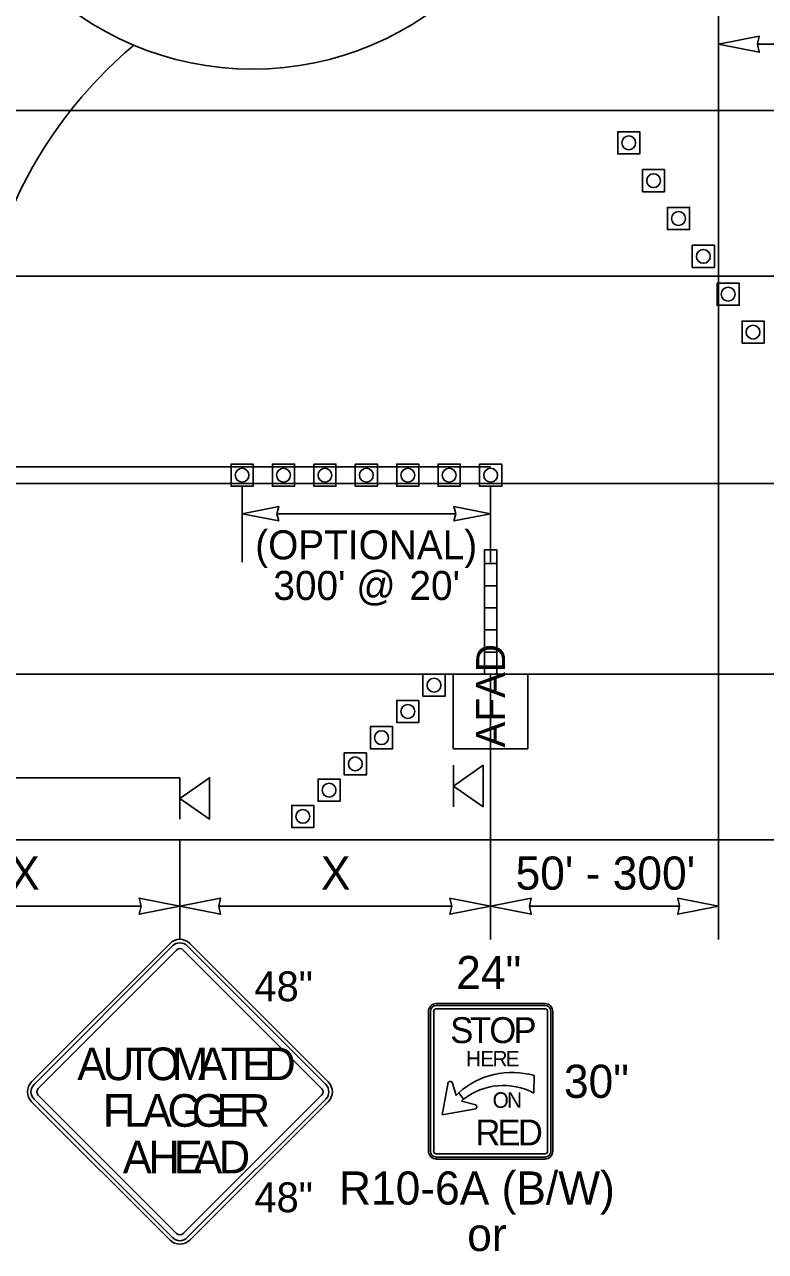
# Model space of a CAD drawing. Extents: x 99999.1 to 100095.7, y 99995 to 100010.7.
# Drawn here: x 100003.152 to 100004.94, y 100004.739 to 100007.7 of the extents above; entities that cross this region are included whole.
import ezdxf

# ---------------------------------------------------------------- set-up
doc = ezdxf.new("R2010")
doc.units = 0
for name, color, linetype in [('RD_ED_ShoulderPavedEdge', 7, 'Continuous'), ('RD_MK_LineDblYellowCenter', 7, 'Continuous'), ('RD_MK_LineEdgeWhite', 7, 'Continuous'), ('RD_MK_LineNoPass', 7, 'Continuous'), ('RD_MK_LineSkipCenter', 7, 'Continuous'), ('TR_SN_ConstructionSigns', 7, 'Continuous'), ('TR_WZ_AFAD', 7, 'Continuous'), ('TR_WZ_PortableSignMountBlk-Org', 7, 'Continuous'), ('TR_WZ_PortableSignMountBlk-Wht', 7, 'Continuous'), ('TR_WZ_TrafficCone', 7, 'Continuous'), ('TR_WZ_WorkZoneDetails', 7, 'Continuous'), ('TR_WZ_WorkZoneTextCurrent', 7, 'Continuous')]:
    doc.layers.add(name, color=color, linetype=linetype)

msp = doc.modelspace()

# ---------------------------------------------------------------- linework, layer by layer
at = {"layer": 'RD_ED_ShoulderPavedEdge'}
for p, q in [((100000.1076, 100007.4923), (100015.6424, 100007.4923)), ((100000.1076, 100005.7323), (100015.6424, 100005.7323))]:
    msp.add_line(p, q, dxfattribs=at)
at = {"layer": 'RD_MK_LineDblYellowCenter'}
for p, q in [((100000.1282, 100006.6323), (100003.4767, 100006.6323)), ((100000.0869, 100006.5923), (100003.4767, 100006.5923))]:
    msp.add_line(p, q, dxfattribs=at)
at = {"layer": 'RD_MK_LineEdgeWhite'}
for p, q in [((100000.1076, 100007.0923), (100015.6424, 100007.0923)), ((100000.1076, 100006.1323), (100015.6424, 100006.1323))]:
    msp.add_line(p, q, dxfattribs=at)
at = {"layer": 'RD_MK_LineNoPass'}
msp.add_line((100003.4767, 100006.6323), (100004.2767, 100006.6323), dxfattribs=at)
at = {"layer": 'RD_MK_LineSkipCenter'}
msp.add_lwpolyline([(100011.15, 100006.5923), (100003.4767, 100006.5923)], dxfattribs=at)
at = {"layer": 'TR_SN_ConstructionSigns'}
for p, q in [((100003.5028, 100005.4824), (100003.1687, 100005.1483)), ((100003.5088, 100005.4765), (100003.1746, 100005.1424)), ((100003.1846, 100005.1324), (100003.5187, 100005.4665)), ((100003.5346, 100005.4665), (100003.8687, 100005.1324)), ((100003.8787, 100005.1424), (100003.5445, 100005.4765)), ((100003.8846, 100005.1483), (100003.5505, 100005.4824)), ((100004.4079, 100005.3373), (100004.1454, 100005.3373)), ((100004.1454, 100005.3373), (100004.4079, 100005.3373)), ((100004.4079, 100005.3373), (100004.1454, 100005.3373)), ((100004.1454, 100005.3373), (100004.4079, 100005.3373)), ((100004.1267, 100005.3186), (100004.1267, 100004.9811)), ((100004.1267, 100004.9811), (100004.1267, 100005.3186)), ((100004.1267, 100005.3186), (100004.1267, 100004.9811)), ((100004.1267, 100004.9811), (100004.1267, 100005.3186)), ((100004.1313, 100005.3186), (100004.1313, 100004.9811)), ((100004.1392, 100004.9811), (100004.1392, 100005.3186)), ((100004.4079, 100005.3326), (100004.1454, 100005.3326)), ((100004.1454, 100005.3248), (100004.4079, 100005.3248)), ((100004.4142, 100005.3186), (100004.4142, 100004.9811)), ((100004.422, 100004.9811), (100004.422, 100005.3186)), ((100004.4267, 100004.9811), (100004.4267, 100005.3186)), ((100004.4267, 100005.3186), (100004.4267, 100004.9811)), ((100004.4267, 100004.9811), (100004.4267, 100005.3186)), ((100004.4267, 100005.3186), (100004.4267, 100004.9811)), ((100004.3816, 100005.1635), (100004.3813, 100005.1216)), ((100004.3813, 100005.1216), (100004.3816, 100005.1635)), ((100004.1595, 100005.0686), (100004.1731, 100005.143)), ((100004.1839, 100005.1479), (100004.1933, 100005.1154)), ((100003.1687, 100005.1006), (100003.5028, 100004.7665)), ((100003.1746, 100005.1066), (100003.5088, 100004.7725)), ((100003.5187, 100004.7824), (100003.1846, 100005.1165)), ((100003.8687, 100005.1165), (100003.5346, 100004.7824)), ((100003.5445, 100004.7725), (100003.8787, 100005.1066)), ((100003.5505, 100004.7665), (100003.8846, 100005.1006)), ((100004.1933, 100005.1154), (100004.1996, 100005.1218)), ((100004.1996, 100005.1218), (100004.2113, 100005.1069)), ((100004.1996, 100005.1218), (100004.2113, 100005.1069)), ((100004.2113, 100005.1069), (100004.2066, 100005.1021)), ((100004.2066, 100005.1021), (100004.2408, 100005.0929)), ((100004.2406, 100005.0837), (100004.1595, 100005.0686)), ((100004.4079, 100004.9748), (100004.1454, 100004.9748)), ((100004.1454, 100004.967), (100004.4079, 100004.967)), ((100004.1454, 100004.9623), (100004.4079, 100004.9623)), ((100004.4079, 100004.9623), (100004.1454, 100004.9623)), ((100004.1454, 100004.9623), (100004.4079, 100004.9623)), ((100004.4079, 100004.9623), (100004.1454, 100004.9623))]:
    msp.add_line(p, q, dxfattribs=at)
for centre, radius, start, end in [((100003.5267, 100005.4586), 0.0338, 45, 135), ((100003.5267, 100005.4586), 0.0253, 45, 135), ((100003.5267, 100005.4586), 0.0113, 45, 135), ((100004.1454, 100005.3186), 0.0187, 90, 180), ((100004.1454, 100005.3186), 0.0187, 90, 180), ((100004.1454, 100005.3186), 0.0187, 90, 180), ((100004.1454, 100005.3186), 0.0187, 90, 180), ((100004.4079, 100005.3186), 0.0187, 0, 90), ((100004.4079, 100005.3186), 0.0187, 0, 90), ((100004.4079, 100005.3186), 0.0187, 0, 90), ((100004.4079, 100005.3186), 0.0187, 0, 90), ((100004.1454, 100005.3186), 0.0141, 90, 180), ((100004.1454, 100005.3186), 0.00625, 90, 180), ((100004.4079, 100005.3186), 0.0141, 0, 90), ((100004.4079, 100005.3186), 0.00625, 0, 90), ((100004.3279, 100004.9804), 0.1909, 73.6434, 132.2131), ((100004.3279, 100004.9804), 0.1909, 73.6434, 132.2131), ((100003.1925, 100005.1245), 0.0338, 135, 225), ((100003.1925, 100005.1245), 0.0253, 135, 225), ((100003.1925, 100005.1245), 0.0113, 135, 225), ((100003.8608, 100005.1245), 0.0113, 315, 45), ((100003.8608, 100005.1245), 0.0253, 315, 45), ((100003.8608, 100005.1245), 0.0338, 315, 45), ((100004.3078, 100004.981), 0.1586, 62.4149, 127.4769), ((100004.3078, 100004.981), 0.1586, 62.4149, 127.4769), ((100004.1454, 100004.9811), 0.0187, 180, 270), ((100004.1454, 100004.9811), 0.0187, 180, 270), ((100004.1454, 100004.9811), 0.0187, 180, 270), ((100004.1454, 100004.9811), 0.0187, 180, 270), ((100004.1454, 100004.9811), 0.0141, 180, 270), ((100004.1454, 100004.9811), 0.00625, 180, 270), ((100004.4079, 100004.9811), 0.0187, 270, 0), ((100004.4079, 100004.9811), 0.0187, 270, 0), ((100004.4079, 100004.9811), 0.0187, 270, 0), ((100004.4079, 100004.9811), 0.0141, 270, 0), ((100004.4079, 100004.9811), 0.00625, 270, 0), ((100004.4079, 100004.9811), 0.0187, 270, 0), ((100003.5267, 100004.7904), 0.0253, 225, 315), ((100003.5267, 100004.7904), 0.0113, 225, 315), ((100003.5267, 100004.7904), 0.0338, 225, 315)]:
    msp.add_arc(centre, radius, start, end, dxfattribs=at)
for centre, major_axis, ratio, start_param, end_param in [((100004.1795, 100005.1431), (-0.00647, -0.00009), 0.989437, 3.962549, 6.283185), ((100004.2384, 100005.0883), (-0.0046, 0.00239), 0.999053, 2.490568, 4.712389)]:
    msp.add_ellipse(centre, major_axis=major_axis, ratio=ratio, start_param=start_param, end_param=end_param, dxfattribs=at)
at = {"layer": 'TR_WZ_AFAD'}
for p, q in [((100004.2916, 100006.399), (100004.2916, 100006.4323)), ((100004.2616, 100006.399), (100004.2616, 100006.3457)), ((100004.2616, 100006.399), (100004.2766, 100006.399)), ((100004.2766, 100006.399), (100004.2916, 100006.399)), ((100004.2916, 100006.3457), (100004.2916, 100006.399)), ((100004.2616, 100006.3457), (100004.2616, 100006.2923)), ((100004.2766, 100006.3457), (100004.2616, 100006.3457)), ((100004.2916, 100006.3457), (100004.2766, 100006.3457)), ((100004.2916, 100006.2923), (100004.2916, 100006.3457)), ((100004.2616, 100006.2923), (100004.2616, 100006.239)), ((100004.2616, 100006.2923), (100004.2766, 100006.2923)), ((100004.2766, 100006.2923), (100004.2916, 100006.2923)), ((100004.2916, 100006.239), (100004.2916, 100006.2923)), ((100004.2766, 100006.239), (100004.2616, 100006.239)), ((100004.2616, 100006.239), (100004.2616, 100006.1857)), ((100004.2916, 100006.239), (100004.2766, 100006.239)), ((100004.2916, 100006.1857), (100004.2916, 100006.239)), ((100004.2616, 100006.1857), (100004.2616, 100006.1323)), ((100004.1866, 100005.9523), (100004.1866, 100006.1323)), ((100004.1866, 100006.1323), (100004.3666, 100006.1323)), ((100004.27, 100006.1323), (100004.1866, 100006.1323)), ((100004.1866, 100006.1323), (100004.1866, 100005.9523)), ((100004.2616, 100006.1323), (100004.27, 100006.1323)), ((100004.27, 100006.1323), (100004.2766, 100006.1323)), ((100004.3666, 100006.1323), (100004.3666, 100005.9523)), ((100004.3666, 100005.9523), (100004.3666, 100006.1323)), ((100004.3666, 100005.9523), (100004.1866, 100005.9523)), ((100004.1866, 100005.9523), (100004.3666, 100005.9523))]:
    msp.add_line(p, q, dxfattribs=at)
for points in [[(100004.2916, 100006.4323), (100004.2616, 100006.4323), (100004.2616, 100006.399)], [(100004.2916, 100006.1323), (100004.2916, 100006.4323), (100004.2616, 100006.4323), (100004.2616, 100006.1323)], [(100004.2916, 100006.399), (100004.2766, 100006.399), (100004.2616, 100006.399)], [(100004.2616, 100006.3457), (100004.2766, 100006.3457), (100004.2916, 100006.3457)], [(100004.2916, 100006.2923), (100004.2766, 100006.2923), (100004.2616, 100006.2923)], [(100004.2616, 100006.239), (100004.2766, 100006.239), (100004.2916, 100006.239)], [(100004.2916, 100006.1857), (100004.2766, 100006.1857), (100004.2616, 100006.1857)], [(100004.2616, 100006.1857), (100004.2766, 100006.1857), (100004.2916, 100006.1857)], [(100004.2766, 100006.1323), (100004.2833, 100006.1323), (100004.2916, 100006.1323), (100004.2916, 100006.1857)], [(100004.3666, 100006.1323), (100004.2833, 100006.1323), (100004.27, 100006.1323)]]:
    msp.add_lwpolyline(points, dxfattribs=at)
at = {"layer": 'TR_WZ_PortableSignMountBlk-Org'}
msp.add_line((100003.5267, 100005.7824), (100003.5267, 100005.8824), dxfattribs=at)
msp.add_lwpolyline([(100003.5267, 100005.8323), (100003.5985, 100005.8824), (100003.5985, 100005.7824)], close=True, dxfattribs=at)
at = {"layer": 'TR_WZ_PortableSignMountBlk-Wht'}
msp.add_line((100004.1867, 100005.8123), (100004.1867, 100005.9123), dxfattribs=at)
msp.add_lwpolyline([(100004.1867, 100005.8622), (100004.2585, 100005.9123), (100004.2585, 100005.8123)], close=True, dxfattribs=at)
at = {"layer": 'TR_WZ_TrafficCone'}
for points in [[(100004.6367, 100007.4411), (100004.5834, 100007.4411), (100004.5834, 100007.3877), (100004.6367, 100007.3877), (100004.6367, 100007.4411)], [(100004.6367, 100007.3877), (100004.5834, 100007.3877), (100004.5834, 100007.4411), (100004.6367, 100007.4411), (100004.6367, 100007.3877)], [(100004.6367, 100007.4411), (100004.5834, 100007.4411), (100004.5834, 100007.3877), (100004.6367, 100007.3877), (100004.6367, 100007.4411)], [(100004.6367, 100007.3877), (100004.5834, 100007.3877), (100004.5834, 100007.4411), (100004.6367, 100007.4411), (100004.6367, 100007.3877)], [(100004.6967, 100007.3497), (100004.6434, 100007.3497), (100004.6434, 100007.2964), (100004.6967, 100007.2964), (100004.6967, 100007.3497)], [(100004.6967, 100007.2964), (100004.6434, 100007.2964), (100004.6434, 100007.3497), (100004.6967, 100007.3497), (100004.6967, 100007.2964)], [(100004.6967, 100007.3497), (100004.6434, 100007.3497), (100004.6434, 100007.2964), (100004.6967, 100007.2964), (100004.6967, 100007.3497)], [(100004.6967, 100007.2964), (100004.6434, 100007.2964), (100004.6434, 100007.3497), (100004.6967, 100007.3497), (100004.6967, 100007.2964)], [(100004.7567, 100007.2584), (100004.7034, 100007.2584), (100004.7034, 100007.2051), (100004.7567, 100007.2051), (100004.7567, 100007.2584)], [(100004.7567, 100007.2051), (100004.7034, 100007.2051), (100004.7034, 100007.2584), (100004.7567, 100007.2584), (100004.7567, 100007.2051)], [(100004.7567, 100007.2584), (100004.7034, 100007.2584), (100004.7034, 100007.2051), (100004.7567, 100007.2051), (100004.7567, 100007.2584)], [(100004.7567, 100007.2051), (100004.7034, 100007.2051), (100004.7034, 100007.2584), (100004.7567, 100007.2584), (100004.7567, 100007.2051)], [(100004.8167, 100007.1671), (100004.7634, 100007.1671), (100004.7634, 100007.1137), (100004.8167, 100007.1137), (100004.8167, 100007.1671)], [(100004.8167, 100007.1137), (100004.7634, 100007.1137), (100004.7634, 100007.1671), (100004.8167, 100007.1671), (100004.8167, 100007.1137)], [(100004.8234, 100007.0757), (100004.8767, 100007.0757), (100004.8767, 100007.0224), (100004.8234, 100007.0224), (100004.8234, 100007.0757)], [(100004.8234, 100007.0224), (100004.8767, 100007.0224), (100004.8767, 100007.0757), (100004.8234, 100007.0757), (100004.8234, 100007.0224)], [(100004.8834, 100006.9844), (100004.9367, 100006.9844), (100004.9367, 100006.9311), (100004.8834, 100006.9311), (100004.8834, 100006.9844)], [(100004.8834, 100006.9311), (100004.9367, 100006.9311), (100004.9367, 100006.9844), (100004.8834, 100006.9844), (100004.8834, 100006.9311)], [(100003.7033, 100006.639), (100003.65, 100006.639), (100003.65, 100006.5857), (100003.7033, 100006.5857), (100003.7033, 100006.639)], [(100003.7033, 100006.5857), (100003.65, 100006.5857), (100003.65, 100006.639), (100003.7033, 100006.639), (100003.7033, 100006.5857)], [(100003.8033, 100006.639), (100003.75, 100006.639), (100003.75, 100006.5857), (100003.8033, 100006.5857), (100003.8033, 100006.639)], [(100003.8033, 100006.5857), (100003.75, 100006.5857), (100003.75, 100006.639), (100003.8033, 100006.639), (100003.8033, 100006.5857)], [(100003.9033, 100006.639), (100003.85, 100006.639), (100003.85, 100006.5857), (100003.9033, 100006.5857), (100003.9033, 100006.639)], [(100003.9033, 100006.5857), (100003.85, 100006.5857), (100003.85, 100006.639), (100003.9033, 100006.639), (100003.9033, 100006.5857)], [(100004.0033, 100006.639), (100003.95, 100006.639), (100003.95, 100006.5857), (100004.0033, 100006.5857), (100004.0033, 100006.639)], [(100004.0033, 100006.5857), (100003.95, 100006.5857), (100003.95, 100006.639), (100004.0033, 100006.639), (100004.0033, 100006.5857)], [(100004.1033, 100006.639), (100004.05, 100006.639), (100004.05, 100006.5857), (100004.1033, 100006.5857), (100004.1033, 100006.639)], [(100004.1033, 100006.5857), (100004.05, 100006.5857), (100004.05, 100006.639), (100004.1033, 100006.639), (100004.1033, 100006.5857)], [(100004.2033, 100006.639), (100004.15, 100006.639), (100004.15, 100006.5857), (100004.2033, 100006.5857), (100004.2033, 100006.639)], [(100004.2033, 100006.5857), (100004.15, 100006.5857), (100004.15, 100006.639), (100004.2033, 100006.639), (100004.2033, 100006.5857)], [(100004.3033, 100006.639), (100004.25, 100006.639), (100004.25, 100006.5857), (100004.3033, 100006.5857), (100004.3033, 100006.639)], [(100004.3033, 100006.5857), (100004.25, 100006.5857), (100004.25, 100006.639), (100004.3033, 100006.639), (100004.3033, 100006.5857)], [(100004.1133, 100006.1323), (100004.1667, 100006.1323), (100004.1667, 100006.079), (100004.1133, 100006.079), (100004.1133, 100006.1323)], [(100004.1133, 100006.079), (100004.1667, 100006.079), (100004.1667, 100006.1323), (100004.1133, 100006.1323), (100004.1133, 100006.079)], [(100004.05, 100006.069), (100004.1033, 100006.069), (100004.1033, 100006.0157), (100004.05, 100006.0157), (100004.05, 100006.069)], [(100004.05, 100006.0157), (100004.1033, 100006.0157), (100004.1033, 100006.069), (100004.05, 100006.069), (100004.05, 100006.0157)], [(100003.9867, 100006.0057), (100004.04, 100006.0057), (100004.04, 100005.9523), (100003.9867, 100005.9523), (100003.9867, 100006.0057)], [(100003.9867, 100005.9523), (100004.04, 100005.9523), (100004.04, 100006.0057), (100003.9867, 100006.0057), (100003.9867, 100005.9523)], [(100003.9767, 100005.9423), (100003.9233, 100005.9423), (100003.9233, 100005.889), (100003.9767, 100005.889), (100003.9767, 100005.9423)], [(100003.9767, 100005.889), (100003.9233, 100005.889), (100003.9233, 100005.9423), (100003.9767, 100005.9423), (100003.9767, 100005.889)], [(100003.9133, 100005.879), (100003.86, 100005.879), (100003.86, 100005.8257), (100003.9133, 100005.8257), (100003.9133, 100005.879)], [(100003.9133, 100005.8257), (100003.86, 100005.8257), (100003.86, 100005.879), (100003.9133, 100005.879), (100003.9133, 100005.8257)], [(100003.85, 100005.8157), (100003.7967, 100005.8157), (100003.7967, 100005.7623), (100003.85, 100005.7623), (100003.85, 100005.8157)], [(100003.85, 100005.7623), (100003.7967, 100005.7623), (100003.7967, 100005.8157), (100003.85, 100005.8157), (100003.85, 100005.7623)]]:
    msp.add_lwpolyline(points, dxfattribs=at)
for centre in [(100004.61, 100007.4144), (100004.61, 100007.4144), (100004.67, 100007.3231), (100004.67, 100007.3231), (100004.73, 100007.2317), (100004.73, 100007.2317), (100004.79, 100007.1404), (100004.85, 100007.0491), (100004.91, 100006.9577), (100003.6767, 100006.6123), (100003.7767, 100006.6123), (100003.8767, 100006.6123), (100003.9767, 100006.6123), (100004.0767, 100006.6123), (100004.1767, 100006.6123), (100004.2767, 100006.6123), (100004.14, 100006.1057), (100004.0767, 100006.0423), (100004.0133, 100005.979), (100003.95, 100005.9157), (100003.8867, 100005.8523), (100003.8233, 100005.789)]:
    msp.add_circle(centre, 0.0167, dxfattribs=at)
at = {"layer": 'TR_WZ_WorkZoneDetails'}
for p, q in [((100004.8267, 100005.4923), (100004.8267, 100007.7323)), ((100004.9204, 100007.6523), (100005.0563, 100007.6523)), ((100003.6767, 100006.5857), (100003.6767, 100006.4023)), ((100004.2767, 100006.5857), (100004.2767, 100006.4023)), ((100004.1923, 100006.5193), (100003.761, 100006.5193)), ((100004.2767, 100006.1323), (100004.2767, 100005.4923)), ((100000.5267, 100005.8824), (100003.5267, 100005.8824)), ((100003.5267, 100005.7323), (100003.5267, 100005.4923)), ((100003.4329, 100005.5723), (100002.8704, 100005.5723)), ((100004.1829, 100005.5723), (100003.6204, 100005.5723)), ((100004.7329, 100005.5723), (100004.3704, 100005.5723))]:
    msp.add_line(p, q, dxfattribs=at)
for points in [[(100004.8267, 100007.6523), (100004.9249, 100007.6331), (100004.9204, 100007.6523), (100004.9249, 100007.6716)], [(100003.6767, 100006.5193), (100003.7651, 100006.502), (100003.761, 100006.5193), (100003.7651, 100006.5367)], [(100004.2767, 100006.5193), (100004.1882, 100006.502), (100004.1923, 100006.5193), (100004.1882, 100006.5367)], [(100003.5267, 100005.5723), (100003.4284, 100005.5916), (100003.4329, 100005.5723), (100003.4284, 100005.5531)], [(100003.5267, 100005.5723), (100003.6249, 100005.5916), (100003.6204, 100005.5723), (100003.6249, 100005.5531)], [(100004.2767, 100005.5723), (100004.1784, 100005.5916), (100004.1829, 100005.5723), (100004.1784, 100005.5531)], [(100004.2767, 100005.5723), (100004.3749, 100005.5916), (100004.3704, 100005.5723), (100004.3749, 100005.5531)], [(100004.8267, 100005.5723), (100004.7284, 100005.5916), (100004.7329, 100005.5723), (100004.7284, 100005.5531)]]:
    msp.add_lwpolyline(points, close=True, dxfattribs=at)
msp.add_circle((100003.7022, 100008.3343), 0.742, dxfattribs=at)
msp.add_arc((100004.1081, 100006.8268), 1.0759, 130.0809, 180.3733, dxfattribs=at)

# ---------------------------------------------------------------- texts
at = {"layer": 'TR_SN_ConstructionSigns'}
for s, height, p in [('24"', 0.08, (100004.1936, 100005.3723)), ('48"', 0.072, (100003.7064, 100005.343)), ('30"', 0.08, (100004.4536, 100005.1098)), ('R10-6A (B/W)', 0.08, (100003.9107, 100004.8523)), ('48"', 0.072, (100003.7064, 100004.8339)), ('or', 0.08, (100004.2201, 100004.7403))]:
    msp.add_text(s, height=height, rotation=360, dxfattribs=at).set_placement(p)
for s, height, p in [('S', 0.0625, (100004.1792, 100005.242)), ('O', 0.0625, (100004.2735, 100005.242)), ('T', 0.0625, (100004.2267, 100005.242)), ('P', 0.0625, (100004.3317, 100005.242)), ('A', 0.0787, (100003.279, 100005.1526)), ('U', 0.0787, (100003.3404, 100005.1526)), ('T', 0.0787, (100003.3955, 100005.1526)), ('O', 0.0787, (100003.4451, 100005.1526)), ('M', 0.0787, (100003.5074, 100005.1526)), ('A', 0.0787, (100003.5704, 100005.1526)), ('T', 0.0787, (100003.6255, 100005.1526)), ('E', 0.0787, (100003.6767, 100005.1526)), ('D', 0.0787, (100003.7302, 100005.1526)), ('H', 0.0375, (100004.217, 100005.1858)), ('E', 0.0375, (100004.2515, 100005.1858)), ('R', 0.0375, (100004.2812, 100005.1858)), ('E', 0.0375, (100004.313, 100005.1858)), ('F', 0.0787, (100003.3408, 100005.0401)), ('L', 0.0787, (100003.392, 100005.0401)), ('A', 0.0787, (100003.4369, 100005.0401)), ('G', 0.0787, (100003.4967, 100005.0401)), ('G', 0.0787, (100003.555, 100005.0401)), ('E', 0.0787, (100003.6149, 100005.0401)), ('R', 0.0787, (100003.6684, 100005.0401)), ('O', 0.0375, (100004.2815, 100005.0858)), ('N', 0.0375, (100004.3164, 100005.0858)), ('R', 0.0625, (100004.2399, 100004.9951)), ('E', 0.0625, (100004.293, 100004.9951)), ('D', 0.0625, (100004.3424, 100004.9951)), ('A', 0.0787, (100003.3888, 100004.9276)), ('H', 0.0787, (100003.4503, 100004.9276)), ('E', 0.0787, (100003.5117, 100004.9276)), ('A', 0.0787, (100003.5589, 100004.9276)), ('D', 0.0787, (100003.6204, 100004.9276))]:
    msp.add_text(s, height=height, dxfattribs=at).set_placement(p)
at = {"layer": 'TR_WZ_AFAD'}
msp.add_text('AFAD', height=0.07, rotation=90, dxfattribs=at).set_placement((100004.3116, 100005.9553))
at = {"layer": 'TR_WZ_WorkZoneTextCurrent'}
for s, p in [('(OPTIONAL)', (100003.7085, 100006.4093)), ("300' @", (100003.7523, 100006.3113)), ("20'", (100004.0807, 100006.3113))]:
    msp.add_text(s, height=0.07, dxfattribs=at).set_placement(p)
for s, p in [('X', (100003.1169, 100005.6123)), ('X', (100003.8669, 100005.6123)), ("50' - 300'", (100004.3369, 100005.6123))]:
    msp.add_text(s, height=0.08, rotation=360, dxfattribs=at).set_placement(p)

doc.saveas('drawing.dxf')
